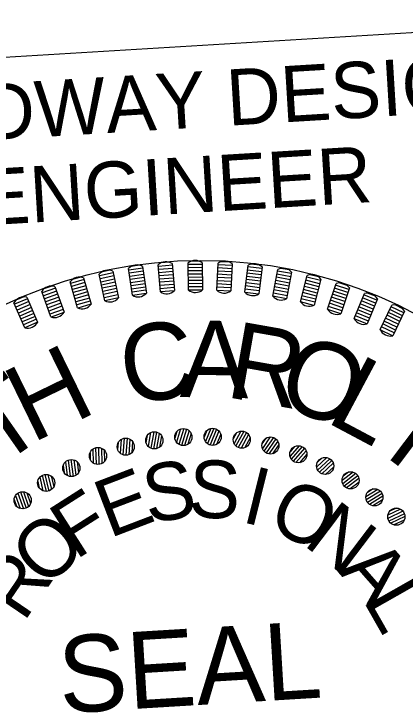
# Model space of a CAD drawing. Extents: x 2111349 to 2114115, y 669753 to 671326.
# Drawn here: x 2113673.4 to 2113708.2, y 670818.6 to 670880.5 of the extents above; entities that cross this region are included whole.
import ezdxf

# ---------------------------------------------------------------- set-up
doc = ezdxf.new("R2010")
doc.units = 0
doc.layers.add('Exist Roads Curbs Text', color=7, linetype='Continuous')
doc.layers.add('Exist Vegetation Woods Line Text', color=7, linetype='Continuous')

msp = doc.modelspace()

# ---------------------------------------------------------------- linework, layer by layer
at = {"layer": 'Exist Roads Curbs Text'}
msp.add_lwpolyline([(2113636.295, 670874.478), (2113736.162, 670880.53), (2113742.968, 670768.236), (2113643.101, 670762.184)], close=True, dxfattribs=at)
at = {"layer": 'Exist Vegetation Woods Line Text'}
for p, q in [((2113684.559, 670858.143), (2113683.805, 670858.035)), ((2113686.417, 670855.789), (2113686.23, 670858.198)), ((2113687.488, 670858.148), (2113686.241, 670858.051)), ((2113687.222, 670858.413), (2113686.463, 670858.355)), ((2113687.476, 670858.295), (2113687.663, 670855.885)), ((2113688.921, 670855.941), (2113688.893, 670858.357)), ((2113690.145, 670858.224), (2113688.895, 670858.21)), ((2113689.898, 670858.507), (2113689.136, 670858.498)), ((2113690.144, 670858.371), (2113690.171, 670855.955)), ((2113691.429, 670855.927), (2113691.562, 670858.34)), ((2113692.802, 670858.125), (2113691.553, 670858.193)), ((2113692.573, 670858.423), (2113691.813, 670858.465)), ((2113692.81, 670858.272), (2113692.677, 670855.858)), ((2113693.931, 670855.748), (2113694.223, 670858.147)), ((2113695.238, 670858.162), (2113694.482, 670858.254)), ((2113681.919, 670857.698), (2113681.174, 670857.54)), ((2113682.187, 670857.614), (2113682.69, 670855.25)), ((2113683.929, 670855.471), (2113683.583, 670857.863)), ((2113684.841, 670857.896), (2113683.604, 670857.717)), ((2113684.882, 670857.614), (2113683.645, 670857.435)), ((2113684.82, 670858.042), (2113685.166, 670855.65)), ((2113687.51, 670857.863), (2113686.264, 670857.767)), ((2113687.532, 670857.579), (2113686.286, 670857.482)), ((2113690.148, 670857.939), (2113688.898, 670857.925)), ((2113690.152, 670857.654), (2113688.902, 670857.64)), ((2113692.77, 670857.555), (2113691.522, 670857.624)), ((2113692.786, 670857.84), (2113691.538, 670857.908)), ((2113695.411, 670857.567), (2113694.17, 670857.718)), ((2113695.446, 670857.85), (2113694.205, 670858.001)), ((2113695.464, 670857.996), (2113695.172, 670855.597)), ((2113696.415, 670855.404), (2113696.865, 670857.778)), ((2113698.066, 670857.401), (2113696.838, 670857.633)), ((2113697.879, 670857.726), (2113697.131, 670857.868)), ((2113698.093, 670857.545), (2113697.644, 670855.171)), ((2113679.314, 670857.079), (2113678.582, 670856.872)), ((2113679.587, 670857.013), (2113680.245, 670854.688)), ((2113681.467, 670854.99), (2113680.964, 670857.354)), ((2113682.217, 670857.47), (2113680.995, 670857.21)), ((2113682.277, 670857.191), (2113681.054, 670856.931)), ((2113682.336, 670856.912), (2113681.113, 670856.652)), ((2113684.923, 670857.331), (2113683.686, 670857.153)), ((2113684.964, 670857.049), (2113683.726, 670856.87)), ((2113687.554, 670857.295), (2113686.308, 670857.198)), ((2113687.576, 670857.01), (2113686.33, 670856.914)), ((2113690.155, 670857.368), (2113688.905, 670857.354)), ((2113690.158, 670857.083), (2113688.908, 670857.069)), ((2113692.739, 670856.985), (2113691.491, 670857.054)), ((2113692.755, 670857.27), (2113691.506, 670857.339)), ((2113695.342, 670857), (2113694.102, 670857.151)), ((2113695.377, 670857.283), (2113694.136, 670857.434)), ((2113697.96, 670856.84), (2113696.732, 670857.073)), ((2113698.013, 670857.12), (2113696.785, 670857.353)), ((2113698.872, 670854.896), (2113699.478, 670857.235)), ((2113700.651, 670856.779), (2113699.441, 670857.093)), ((2113700.486, 670857.117), (2113699.749, 670857.308)), ((2113700.688, 670856.922), (2113700.082, 670854.582)), ((2113676.756, 670856.29), (2113676.039, 670856.034)), ((2113679.042, 670854.347), (2113678.384, 670856.673)), ((2113679.627, 670856.871), (2113678.424, 670856.531)), ((2113679.705, 670856.597), (2113678.502, 670856.257)), ((2113679.783, 670856.322), (2113678.58, 670855.982)), ((2113682.395, 670856.633), (2113681.173, 670856.373)), ((2113682.455, 670856.354), (2113681.232, 670856.094)), ((2113685.004, 670856.767), (2113683.767, 670856.588)), ((2113685.045, 670856.484), (2113683.808, 670856.306)), ((2113687.598, 670856.726), (2113686.352, 670856.629)), ((2113687.62, 670856.441), (2113686.374, 670856.345)), ((2113690.161, 670856.798), (2113688.911, 670856.784)), ((2113690.164, 670856.513), (2113688.914, 670856.499)), ((2113692.708, 670856.416), (2113691.459, 670856.484)), ((2113692.723, 670856.7), (2113691.475, 670856.769)), ((2113695.239, 670856.151), (2113693.998, 670856.302)), ((2113695.274, 670856.434), (2113694.033, 670856.585)), ((2113695.308, 670856.717), (2113694.067, 670856.868)), ((2113697.854, 670856.28), (2113696.625, 670856.512)), ((2113697.907, 670856.56), (2113696.679, 670856.793)), ((2113700.508, 670856.227), (2113699.298, 670856.541)), ((2113700.579, 670856.503), (2113699.369, 670856.817)), ((2113701.289, 670854.227), (2113702.048, 670856.521)), ((2113703.189, 670855.989), (2113702.002, 670856.381)), ((2113703.047, 670856.336), (2113702.324, 670856.576)), ((2113676.665, 670853.546), (2113675.855, 670855.823)), ((2113677.082, 670856.103), (2113675.905, 670855.684)), ((2113677.178, 670855.834), (2113676, 670855.415)), ((2113677.033, 670856.242), (2113677.843, 670853.965)), ((2113679.86, 670856.048), (2113678.657, 670855.708)), ((2113679.938, 670855.773), (2113678.735, 670855.433)), ((2113682.514, 670856.075), (2113681.291, 670855.815)), ((2113682.573, 670855.796), (2113681.351, 670855.536)), ((2113685.086, 670856.202), (2113683.849, 670856.023)), ((2113685.127, 670855.92), (2113683.89, 670855.741)), ((2113687.642, 670856.157), (2113686.396, 670856.06)), ((2113687.649, 670855.871), (2113686.433, 670855.777)), ((2113690.167, 670856.227), (2113688.917, 670856.213)), ((2113690.155, 670855.942), (2113688.936, 670855.928)), ((2113692.692, 670856.131), (2113691.444, 670856.199)), ((2113692.661, 670855.847), (2113691.444, 670855.914)), ((2113695.155, 670855.586), (2113693.945, 670855.734)), ((2113695.205, 670855.868), (2113693.964, 670856.019)), ((2113697.694, 670855.439), (2113696.466, 670855.672)), ((2113697.747, 670855.719), (2113696.519, 670855.952)), ((2113697.801, 670855.999), (2113696.572, 670856.232)), ((2113700.293, 670855.399), (2113699.083, 670855.712)), ((2113700.365, 670855.675), (2113699.155, 670855.988)), ((2113700.436, 670855.951), (2113699.226, 670856.264)), ((2113703.01, 670855.447), (2113701.823, 670855.84)), ((2113703.099, 670855.718), (2113701.913, 670856.111)), ((2113703.235, 670856.129), (2113702.476, 670853.834)), ((2113705.55, 670855.388), (2113704.845, 670855.675)), ((2113674.594, 670855.168), (2113673.446, 670854.672)), ((2113674.256, 670855.333), (2113673.557, 670855.031)), ((2113674.535, 670855.303), (2113675.494, 670853.085)), ((2113677.274, 670855.565), (2113676.096, 670855.146)), ((2113677.369, 670855.297), (2113676.191, 670854.878)), ((2113680.015, 670855.499), (2113678.813, 670855.159)), ((2113680.093, 670855.225), (2113678.89, 670854.884)), ((2113682.633, 670855.517), (2113681.41, 670855.257)), ((2113682.677, 670855.235), (2113681.485, 670854.981)), ((2113685.152, 670855.635), (2113683.946, 670855.461)), ((2113697.626, 670855.161), (2113696.428, 670855.388)), ((2113700.15, 670854.846), (2113698.94, 670855.16)), ((2113700.222, 670855.123), (2113699.012, 670855.436)), ((2113702.831, 670854.906), (2113701.644, 670855.298)), ((2113702.92, 670855.176), (2113701.733, 670855.569)), ((2113703.657, 670853.4), (2113704.566, 670855.639)), ((2113705.562, 670854.768), (2113704.404, 670855.238)), ((2113705.669, 670855.032), (2113704.511, 670855.502)), ((2113705.725, 670855.169), (2113704.816, 670852.929)), ((2113674.347, 670852.589), (2113673.388, 670854.807)), ((2113674.707, 670854.906), (2113673.559, 670854.41)), ((2113674.82, 670854.644), (2113673.673, 670854.148)), ((2113677.465, 670855.028), (2113676.287, 670854.609)), ((2113677.56, 670854.759), (2113676.383, 670854.34)), ((2113677.656, 670854.49), (2113676.478, 670854.071)), ((2113680.171, 670854.95), (2113678.968, 670854.61)), ((2113680.234, 670854.671), (2113679.061, 670854.339)), ((2113700.064, 670854.574), (2113698.884, 670854.88)), ((2113702.562, 670854.093), (2113701.375, 670854.486)), ((2113702.651, 670854.364), (2113701.465, 670854.757)), ((2113702.741, 670854.635), (2113701.554, 670855.027)), ((2113705.24, 670853.975), (2113704.082, 670854.445)), ((2113705.347, 670854.239), (2113704.189, 670854.709)), ((2113705.455, 670854.504), (2113704.296, 670854.974)), ((2113705.965, 670852.418), (2113707.021, 670854.592)), ((2113708.081, 670853.914), (2113706.956, 670854.459)), ((2113707.986, 670854.277), (2113707.301, 670854.609)), ((2113674.933, 670854.382), (2113673.786, 670853.886)), ((2113675.046, 670854.121), (2113673.899, 670853.625)), ((2113675.16, 670853.859), (2113674.012, 670853.363)), ((2113677.752, 670854.222), (2113676.574, 670853.803)), ((2113677.833, 670853.948), (2113676.684, 670853.539)), ((2113702.457, 670853.827), (2113701.3, 670854.21)), ((2113705.025, 670853.446), (2113703.867, 670853.917)), ((2113705.133, 670853.711), (2113703.975, 670854.181)), ((2113707.832, 670853.4), (2113706.707, 670853.946)), ((2113707.956, 670853.657), (2113706.832, 670854.203)), ((2113708.145, 670854.046), (2113707.09, 670851.872)), ((2113675.273, 670853.597), (2113674.125, 670853.101)), ((2113675.386, 670853.335), (2113674.239, 670852.839)), ((2113704.796, 670852.924), (2113703.667, 670853.382)), ((2113704.918, 670853.182), (2113703.76, 670853.652)), ((2113707.583, 670852.887), (2113706.458, 670853.433)), ((2113707.707, 670853.144), (2113706.583, 670853.689)), ((2113675.485, 670853.067), (2113674.366, 670852.583)), ((2113707.209, 670852.117), (2113706.085, 670852.663)), ((2113707.334, 670852.374), (2113706.209, 670852.92)), ((2113707.458, 670852.63), (2113706.334, 670853.176)), ((2113707.071, 670851.867), (2113705.974, 670852.4)), ((2113685.821, 670843.314), (2113685.551, 670841.862)), ((2113686.074, 670843.288), (2113685.797, 670841.795)), ((2113687.878, 670843.341), (2113687.703, 670842.751)), ((2113688.21, 670843.568), (2113687.857, 670842.379)), ((2113688.487, 670843.609), (2113688.067, 670842.193)), ((2113688.737, 670843.557), (2113688.305, 670842.101)), ((2113688.961, 670843.42), (2113688.568, 670842.093)), ((2113690.535, 670843.421), (2113690.3, 670842.852)), ((2113690.89, 670843.612), (2113690.415, 670842.466)), ((2113691.17, 670843.624), (2113690.604, 670842.26)), ((2113691.413, 670843.546), (2113690.831, 670842.143)), ((2113691.622, 670843.387), (2113691.091, 670842.108)), ((2113693.56, 670843.375), (2113692.968, 670842.286)), ((2113693.839, 670843.358), (2113693.134, 670842.061)), ((2113683.2, 670842.742), (2113683.084, 670841.27)), ((2113683.455, 670842.743), (2113683.335, 670841.229)), ((2113685.243, 670842.983), (2113685.13, 670842.378)), ((2113685.549, 670843.244), (2113685.323, 670842.025)), ((2113686.312, 670843.176), (2113686.059, 670841.815)), ((2113686.527, 670842.943), (2113686.344, 670841.955)), ((2113689.151, 670843.166), (2113688.865, 670842.203)), ((2113691.784, 670843.114), (2113691.399, 670842.186)), ((2113693.187, 670843.222), (2113692.893, 670842.682)), ((2113694.073, 670843.255), (2113693.347, 670841.921)), ((2113694.264, 670843.075), (2113693.603, 670841.859)), ((2113694.396, 670842.787), (2113693.916, 670841.904)), ((2113695.804, 670842.748), (2113695.455, 670842.241)), ((2113696.19, 670842.861), (2113695.487, 670841.84)), ((2113696.466, 670842.815), (2113695.63, 670841.598)), ((2113696.688, 670842.688), (2113695.827, 670841.437)), ((2113682.659, 670842.352), (2113682.611, 670841.739)), ((2113682.937, 670842.644), (2113682.84, 670841.408)), ((2113683.703, 670842.656), (2113683.594, 670841.276)), ((2113683.941, 670842.447), (2113683.862, 670841.445)), ((2113696.859, 670842.489), (2113696.074, 670841.348)), ((2113696.961, 670842.189), (2113696.391, 670841.36)), ((2113698.752, 670842.075), (2113697.947, 670841.132)), ((2113680.156, 670841.455), (2113680.172, 670840.84)), ((2113680.402, 670841.774), (2113680.434, 670840.534)), ((2113680.653, 670841.899), (2113680.691, 670840.423)), ((2113680.907, 670841.926), (2113680.946, 670840.408)), ((2113681.162, 670841.866), (2113681.198, 670840.482)), ((2113681.421, 670841.683), (2113681.447, 670840.678)), ((2113698.356, 670842.003), (2113697.956, 670841.535)), ((2113699.022, 670842), (2113698.063, 670840.877)), ((2113699.229, 670841.851), (2113698.242, 670840.696)), ((2113699.379, 670841.635), (2113698.479, 670840.582)), ((2113678.458, 670840.848), (2113678.655, 670839.342)), ((2113678.718, 670840.815), (2113678.899, 670839.442)), ((2113699.449, 670841.326), (2113698.795, 670840.561)), ((2113701.218, 670841.025), (2113700.319, 670840.172)), ((2113700.817, 670840.995), (2113700.37, 670840.571)), ((2113701.479, 670840.922), (2113700.408, 670839.906)), ((2113677.761, 670840.301), (2113677.841, 670839.691)), ((2113677.972, 670840.644), (2113678.133, 670839.414)), ((2113678.208, 670840.794), (2113678.401, 670839.33)), ((2113678.995, 670840.66), (2113679.126, 670839.663)), ((2113701.669, 670840.752), (2113700.567, 670839.707)), ((2113701.795, 670840.522), (2113700.791, 670839.569)), ((2113701.832, 670840.207), (2113701.103, 670839.515)), ((2113703.561, 670839.723), (2113702.577, 670838.969)), ((2113703.81, 670839.594), (2113702.638, 670838.695)), ((2113703.159, 670839.735), (2113702.67, 670839.36)), ((2113675.673, 670839.266), (2113675.962, 670838.06)), ((2113675.893, 670839.44), (2113676.237, 670838.004)), ((2113676.135, 670839.52), (2113676.489, 670838.043)), ((2113676.397, 670839.514), (2113676.72, 670838.167)), ((2113676.689, 670839.389), (2113676.923, 670838.411)), ((2113703.981, 670839.405), (2113702.776, 670838.481)), ((2113704.082, 670839.163), (2113702.984, 670838.32)), ((2113675.499, 670838.903), (2113675.642, 670838.304)), ((2113704.086, 670838.846), (2113703.289, 670838.234)), ((2113673.731, 670837.851), (2113674.223, 670836.459)), ((2113673.963, 670837.956), (2113674.47, 670836.524)), ((2113674.225, 670837.977), (2113674.687, 670836.672)), ((2113674.528, 670837.883), (2113674.863, 670836.936)), ((2113705.755, 670838.184), (2113704.697, 670837.536)), ((2113705.988, 670838.029), (2113704.729, 670837.258)), ((2113705.356, 670838.237), (2113704.831, 670837.916)), ((2113706.139, 670837.823), (2113704.844, 670837.03)), ((2113673.396, 670837.276), (2113673.601, 670836.696)), ((2113673.531, 670837.655), (2113673.945, 670836.486)), ((2113706.215, 670837.572), (2113705.034, 670836.848)), ((2113706.186, 670837.256), (2113705.328, 670836.731)), ((2113707.385, 670836.518), (2113706.829, 670836.254)), ((2113707.776, 670836.423), (2113706.656, 670835.89)), ((2113707.992, 670836.245), (2113706.659, 670835.61)), ((2113708.12, 670836.025), (2113706.749, 670835.371)), ((2113708.169, 670835.766), (2113706.919, 670835.171)), ((2113708.107, 670835.455), (2113707.2, 670835.023))]:
    msp.add_line(p, q, dxfattribs=at)
for centre, radius in [((2113690.024, 670818.026), 40.556), ((2113685.872, 670842.553), 0.762), ((2113688.459, 670842.847), 0.762), ((2113691.062, 670842.869), 0.762), ((2113693.653, 670842.619), 0.762), ((2113683.33, 670841.991), 0.762), ((2113696.204, 670842.099), 0.762), ((2113698.686, 670841.316), 0.762), ((2113680.861, 670841.166), 0.762), ((2113678.492, 670840.087), 0.762), ((2113701.073, 670840.277), 0.762), ((2113703.339, 670838.994), 0.762), ((2113676.249, 670838.766), 0.762), ((2113674.156, 670837.218), 0.762), ((2113705.458, 670837.482), 0.762), ((2113707.407, 670835.756), 0.762)]:
    msp.add_circle(centre, radius, dxfattribs=at)
for centre, radius, start, end in [((2113684.319, 670857.14), 1.032, 60.94889, 135.48986), ((2113686.917, 670857.427), 1.032, 57.15942, 131.70038), ((2113689.528, 670857.543), 1.032, 53.36994, 127.91091), ((2113692.141, 670857.486), 1.032, 49.58047, 124.12144), ((2113694.744, 670857.256), 1.032, 45.79099, 120.33196), ((2113681.746, 670856.681), 1.032, 64.73836, 139.27933), ((2113697.326, 670856.855), 1.032, 42.00152, 116.54249), ((2113679.209, 670856.053), 1.032, 68.52784, 143.0688), ((2113699.877, 670856.284), 1.032, 38.21205, 112.75302), ((2113676.719, 670855.258), 1.032, 72.31731, 146.85828), ((2113702.384, 670855.545), 1.032, 34.42257, 108.96354), ((2113686.981, 670856.593), 0.983, 234.93315, 313.92665), ((2113689.537, 670856.706), 0.983, 231.14368, 310.13717), ((2113692.095, 670856.65), 0.983, 227.35421, 306.3477), ((2113694.643, 670856.425), 0.983, 223.56473, 302.55822), ((2113704.837, 670854.643), 1.032, 30.6331, 105.17407), ((2113674.287, 670854.301), 1.032, 76.10678, 150.64775), ((2113681.92, 670855.862), 0.983, 242.5121, 321.50559), ((2113684.439, 670856.311), 0.983, 238.72263, 317.71612), ((2113697.171, 670856.032), 0.983, 219.77526, 298.76875), ((2113679.437, 670855.247), 0.983, 246.30157, 325.29507), ((2113699.667, 670855.473), 0.983, 215.98578, 294.97928), ((2113707.224, 670853.58), 1.032, 26.84363, 101.38459), ((2113677, 670854.47), 0.983, 250.09105, 329.08454), ((2113702.121, 670854.75), 0.983, 212.19631, 291.1898), ((2113704.522, 670853.867), 0.983, 208.40684, 287.40033), ((2113674.62, 670853.533), 0.983, 253.88052, 332.87401), ((2113706.859, 670852.827), 0.983, 204.61736, 283.61086)]:
    msp.add_arc(centre, radius, start, end, dxfattribs=at)

# ---------------------------------------------------------------- texts
at = {"layer": 'Exist Roads Curbs Text'}
for s, p in [('ROADWAY DESIGN', (2113656.101, 670868.365)), ('ENGINEER', (2113670.483, 670861.672))]:
    msp.add_text(s, height=5.0001, rotation=3.46824, dxfattribs=at).set_placement(p)
at = {"layer": 'Exist Vegetation Woods Line Text'}
for s, height, rotation, p in [('C', 6.846, 7.98253, (2113683.32, 670845.723)), ('A', 6.846, 358.98253, (2113688.126, 670846.415)), ('R', 6.846, 349.98253, (2113692.077, 670846.445)), ('O', 6.846, 340.98253, (2113696.497, 670845.765)), ('H', 6.846, 25.98253, (2113674.968, 670842.255)), ('L', 6.846, 331.98253, (2113700.987, 670844.28)), ('T', 6.846, 34.98253, (2113672.003, 670840.059)), ('I', 6.846, 322.98253, (2113706.208, 670841.291)), ('S', 5.135, 357.67608, (2113688.852, 670835.724)), ('S', 5.135, 9.28898, (2113685.312, 670835.136)), ('E', 5.135, 20.90189, (2113681.877, 670833.816)), ('I', 5.135, 346.06318, (2113693.506, 670835.321)), ('O', 5.135, 334.45027, (2113695.758, 670834.809)), ('F', 5.135, 32.51479, (2113678.863, 670831.864)), ('N', 5.135, 322.83737, (2113699.019, 670833.3)), ('O', 5.135, 44.12769, (2113676.239, 670829.281)), ('A', 5.135, 311.22447, (2113702.15, 670830.89)), ('R', 5.135, 55.7406, (2113674.254, 670826.286)), ('L', 5.135, 299.61156, (2113704.4, 670828.334)), ('SEAL', 6.8461, 3.48253, (2113677.545, 670818.238))]:
    msp.add_text(s, height=height, rotation=rotation, dxfattribs=at).set_placement(p)

doc.saveas('drawing.dxf')
